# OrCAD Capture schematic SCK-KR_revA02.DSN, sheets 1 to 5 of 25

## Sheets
1 Title Page
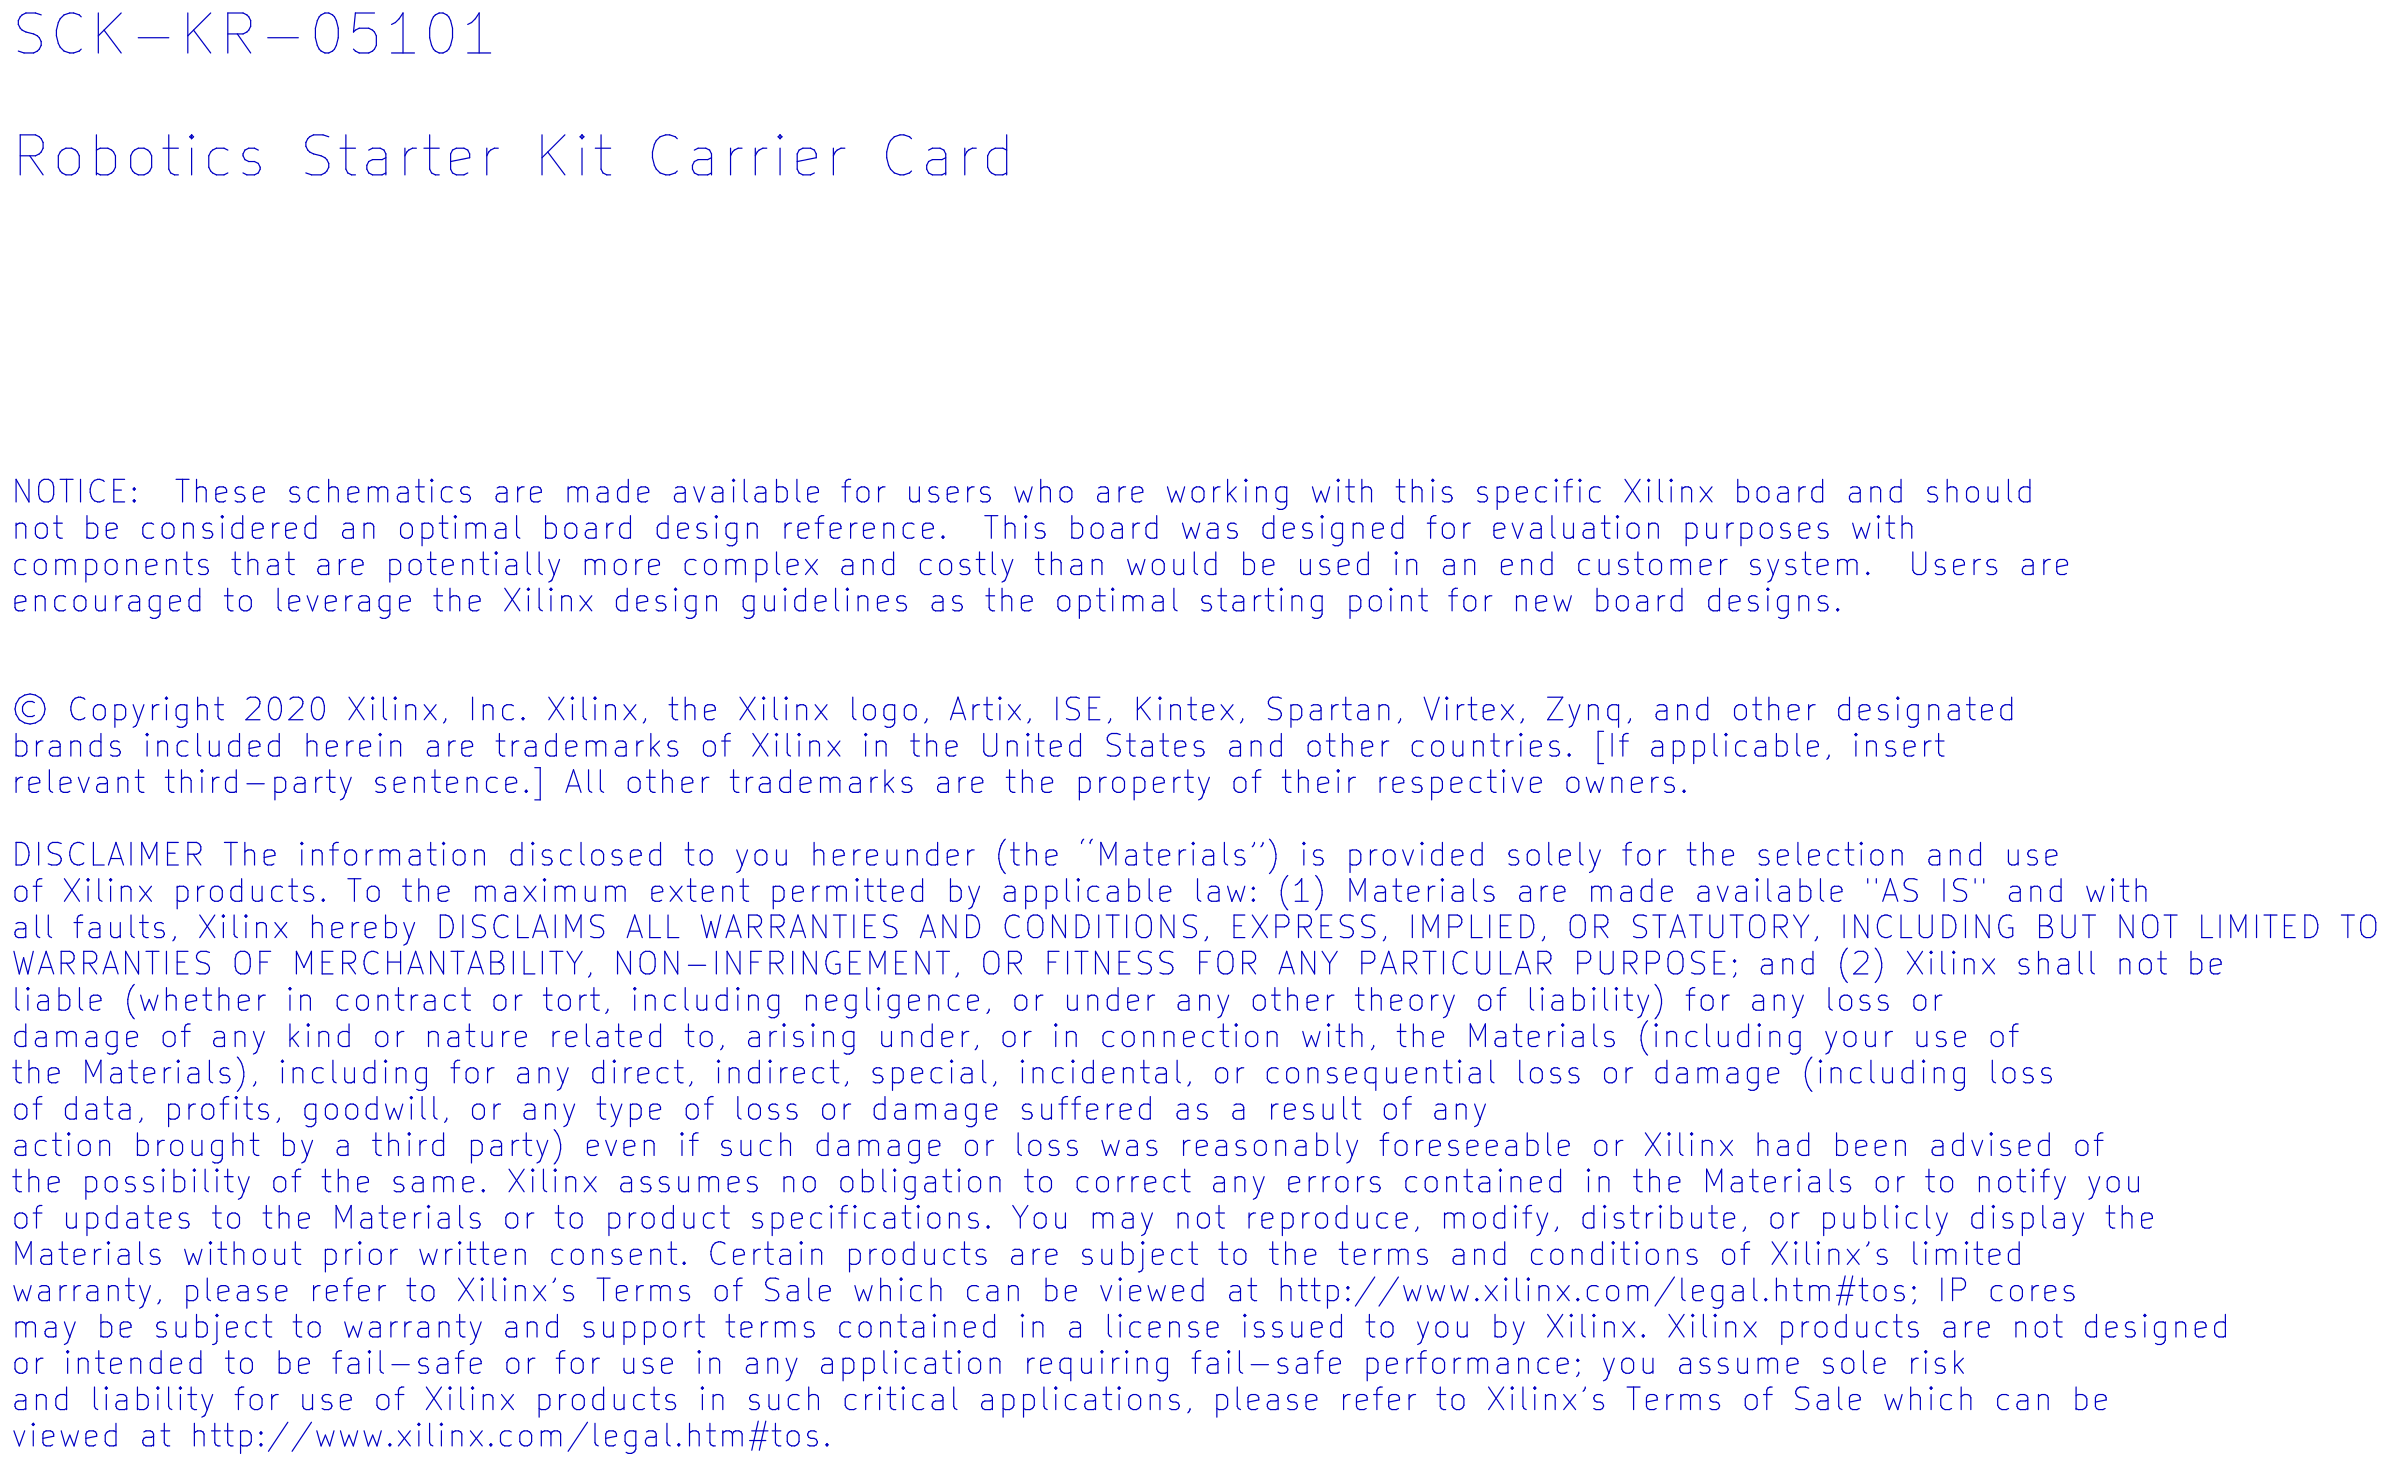
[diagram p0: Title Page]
2 Block Diagram
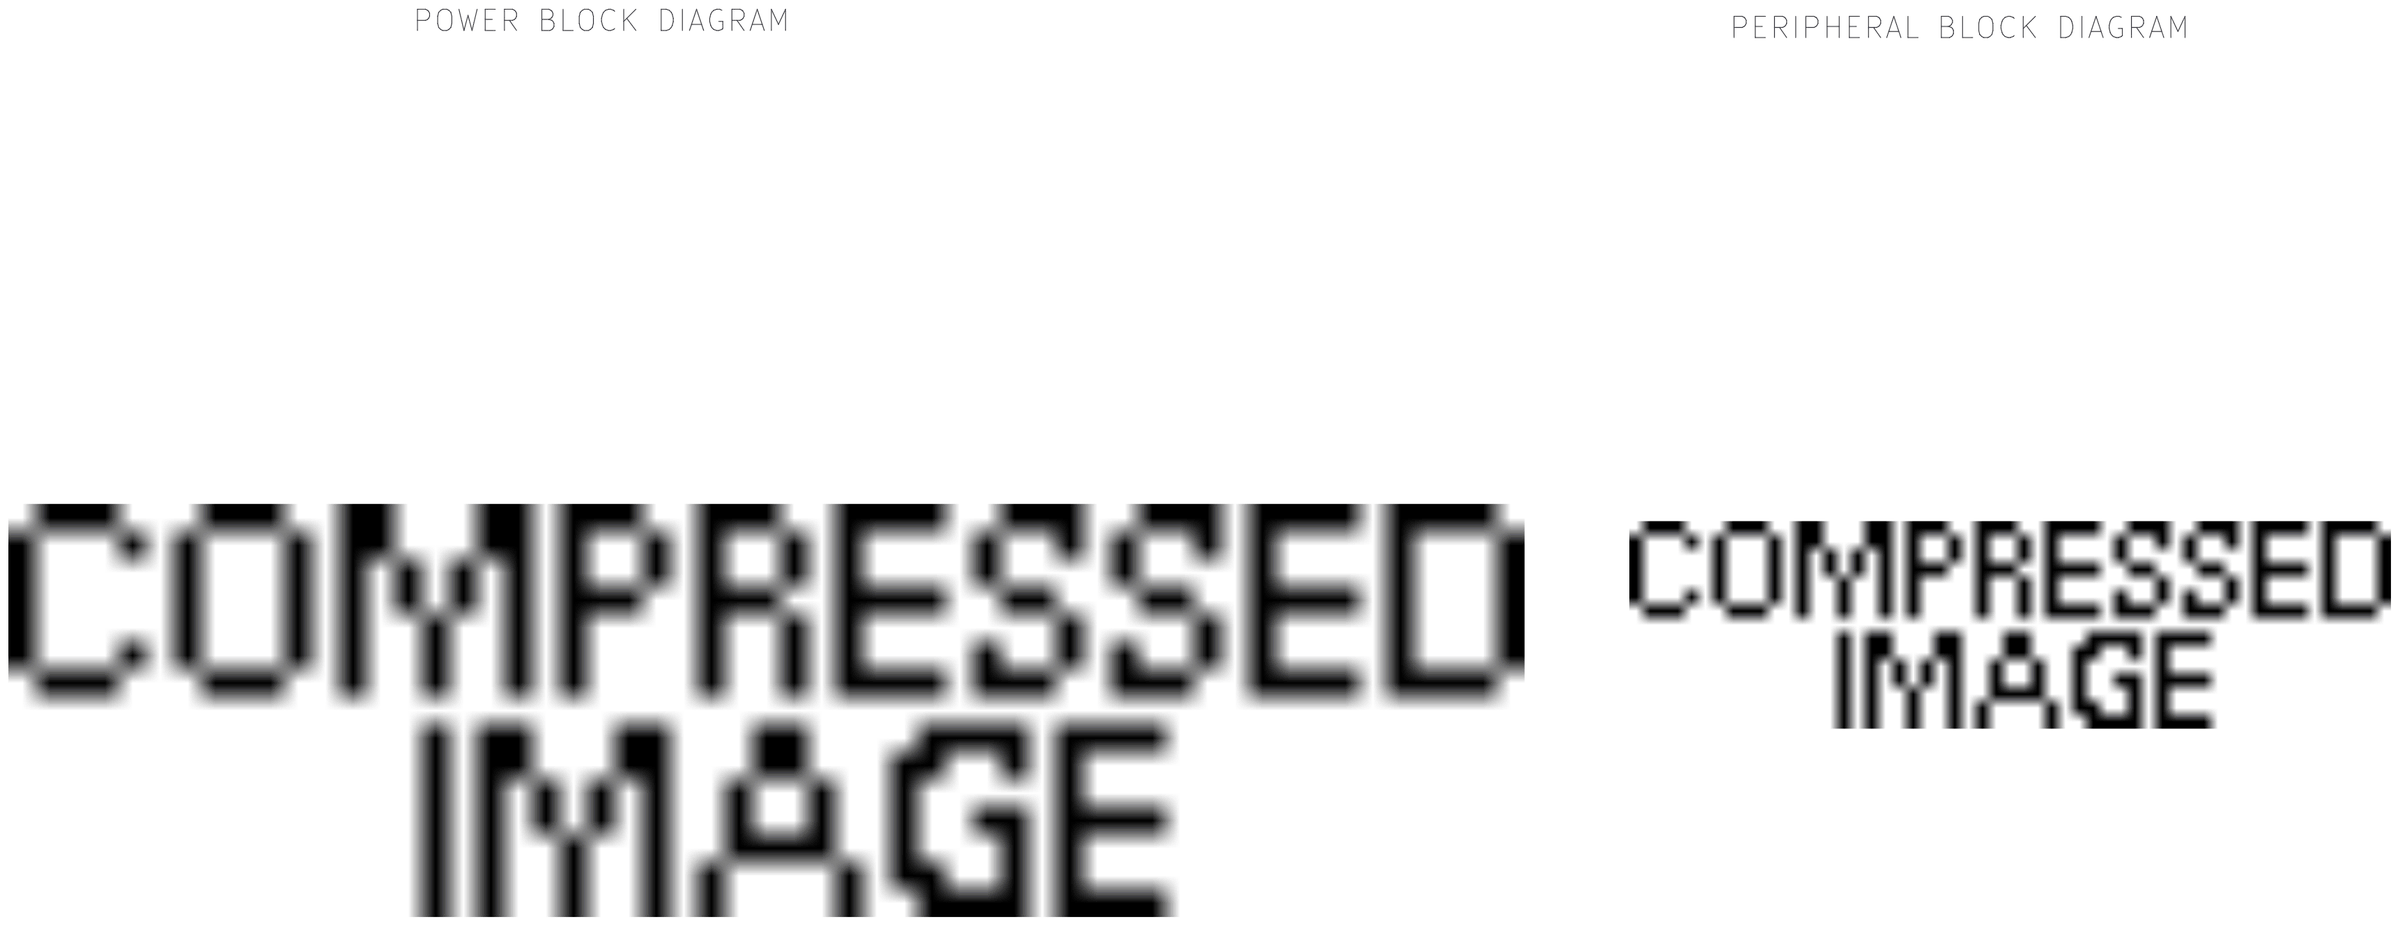
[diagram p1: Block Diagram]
3 Always On Pwr, Fan Header: size Custom
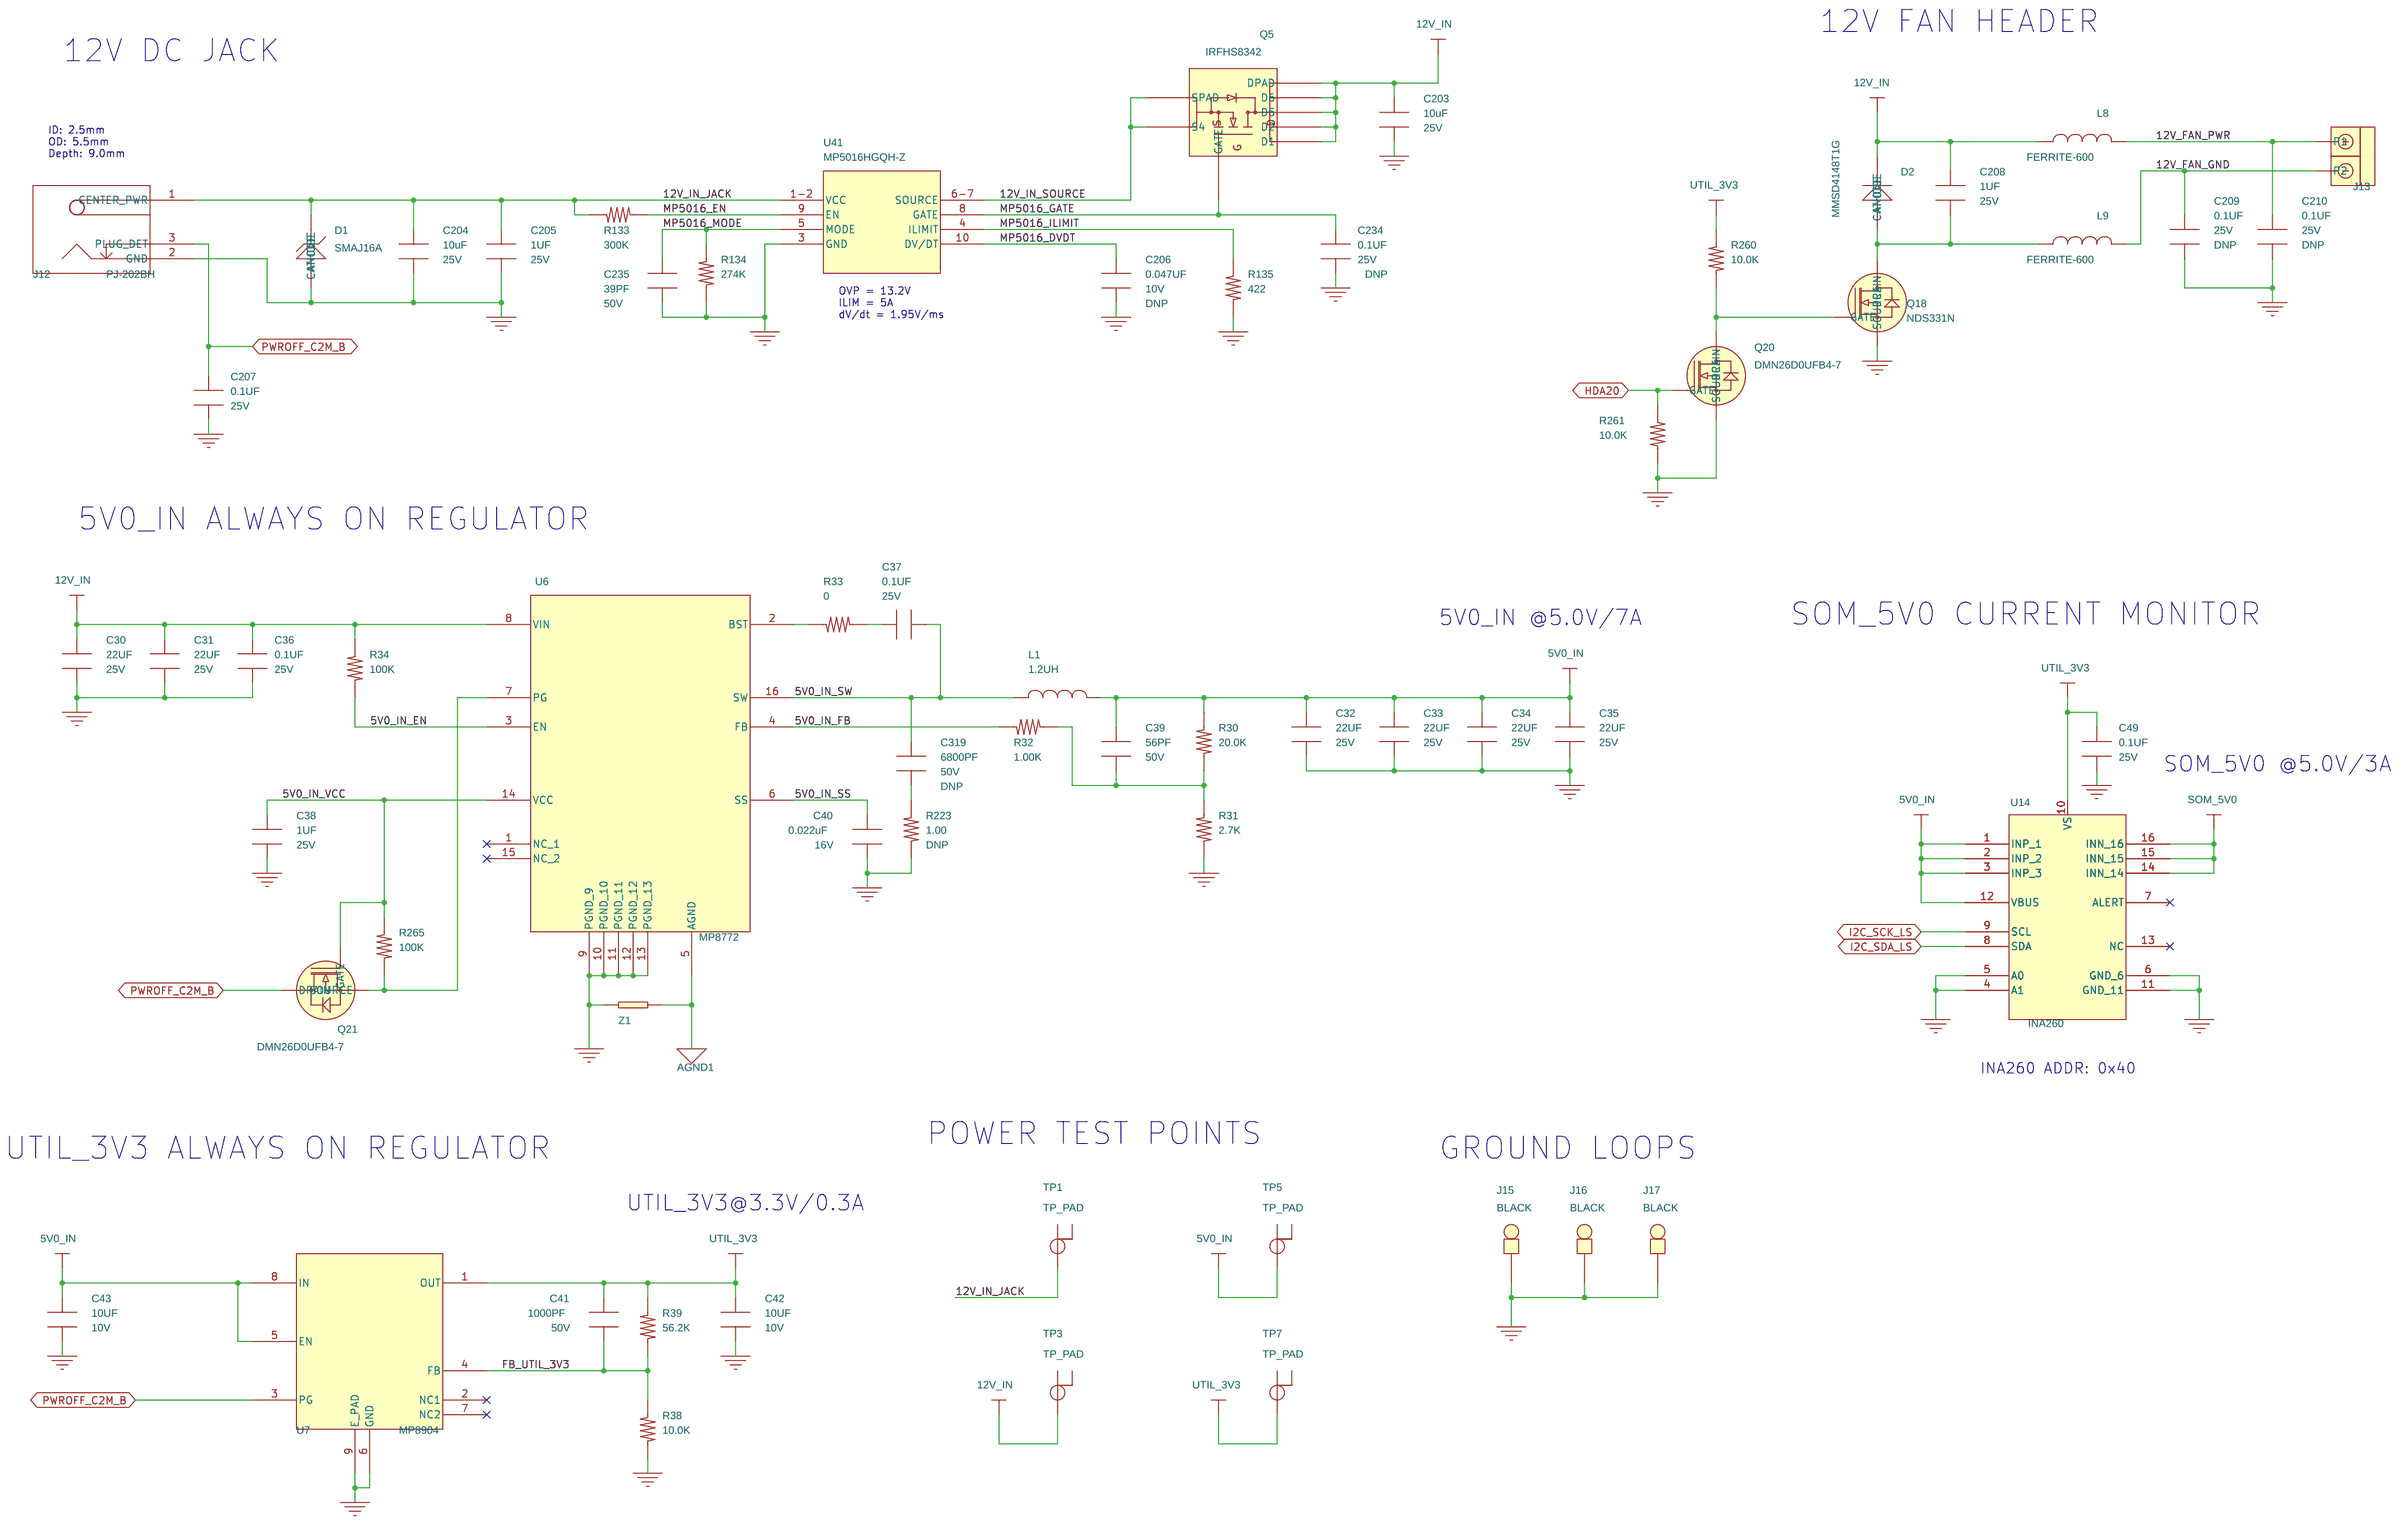
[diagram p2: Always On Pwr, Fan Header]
4 PS Power: size Custom
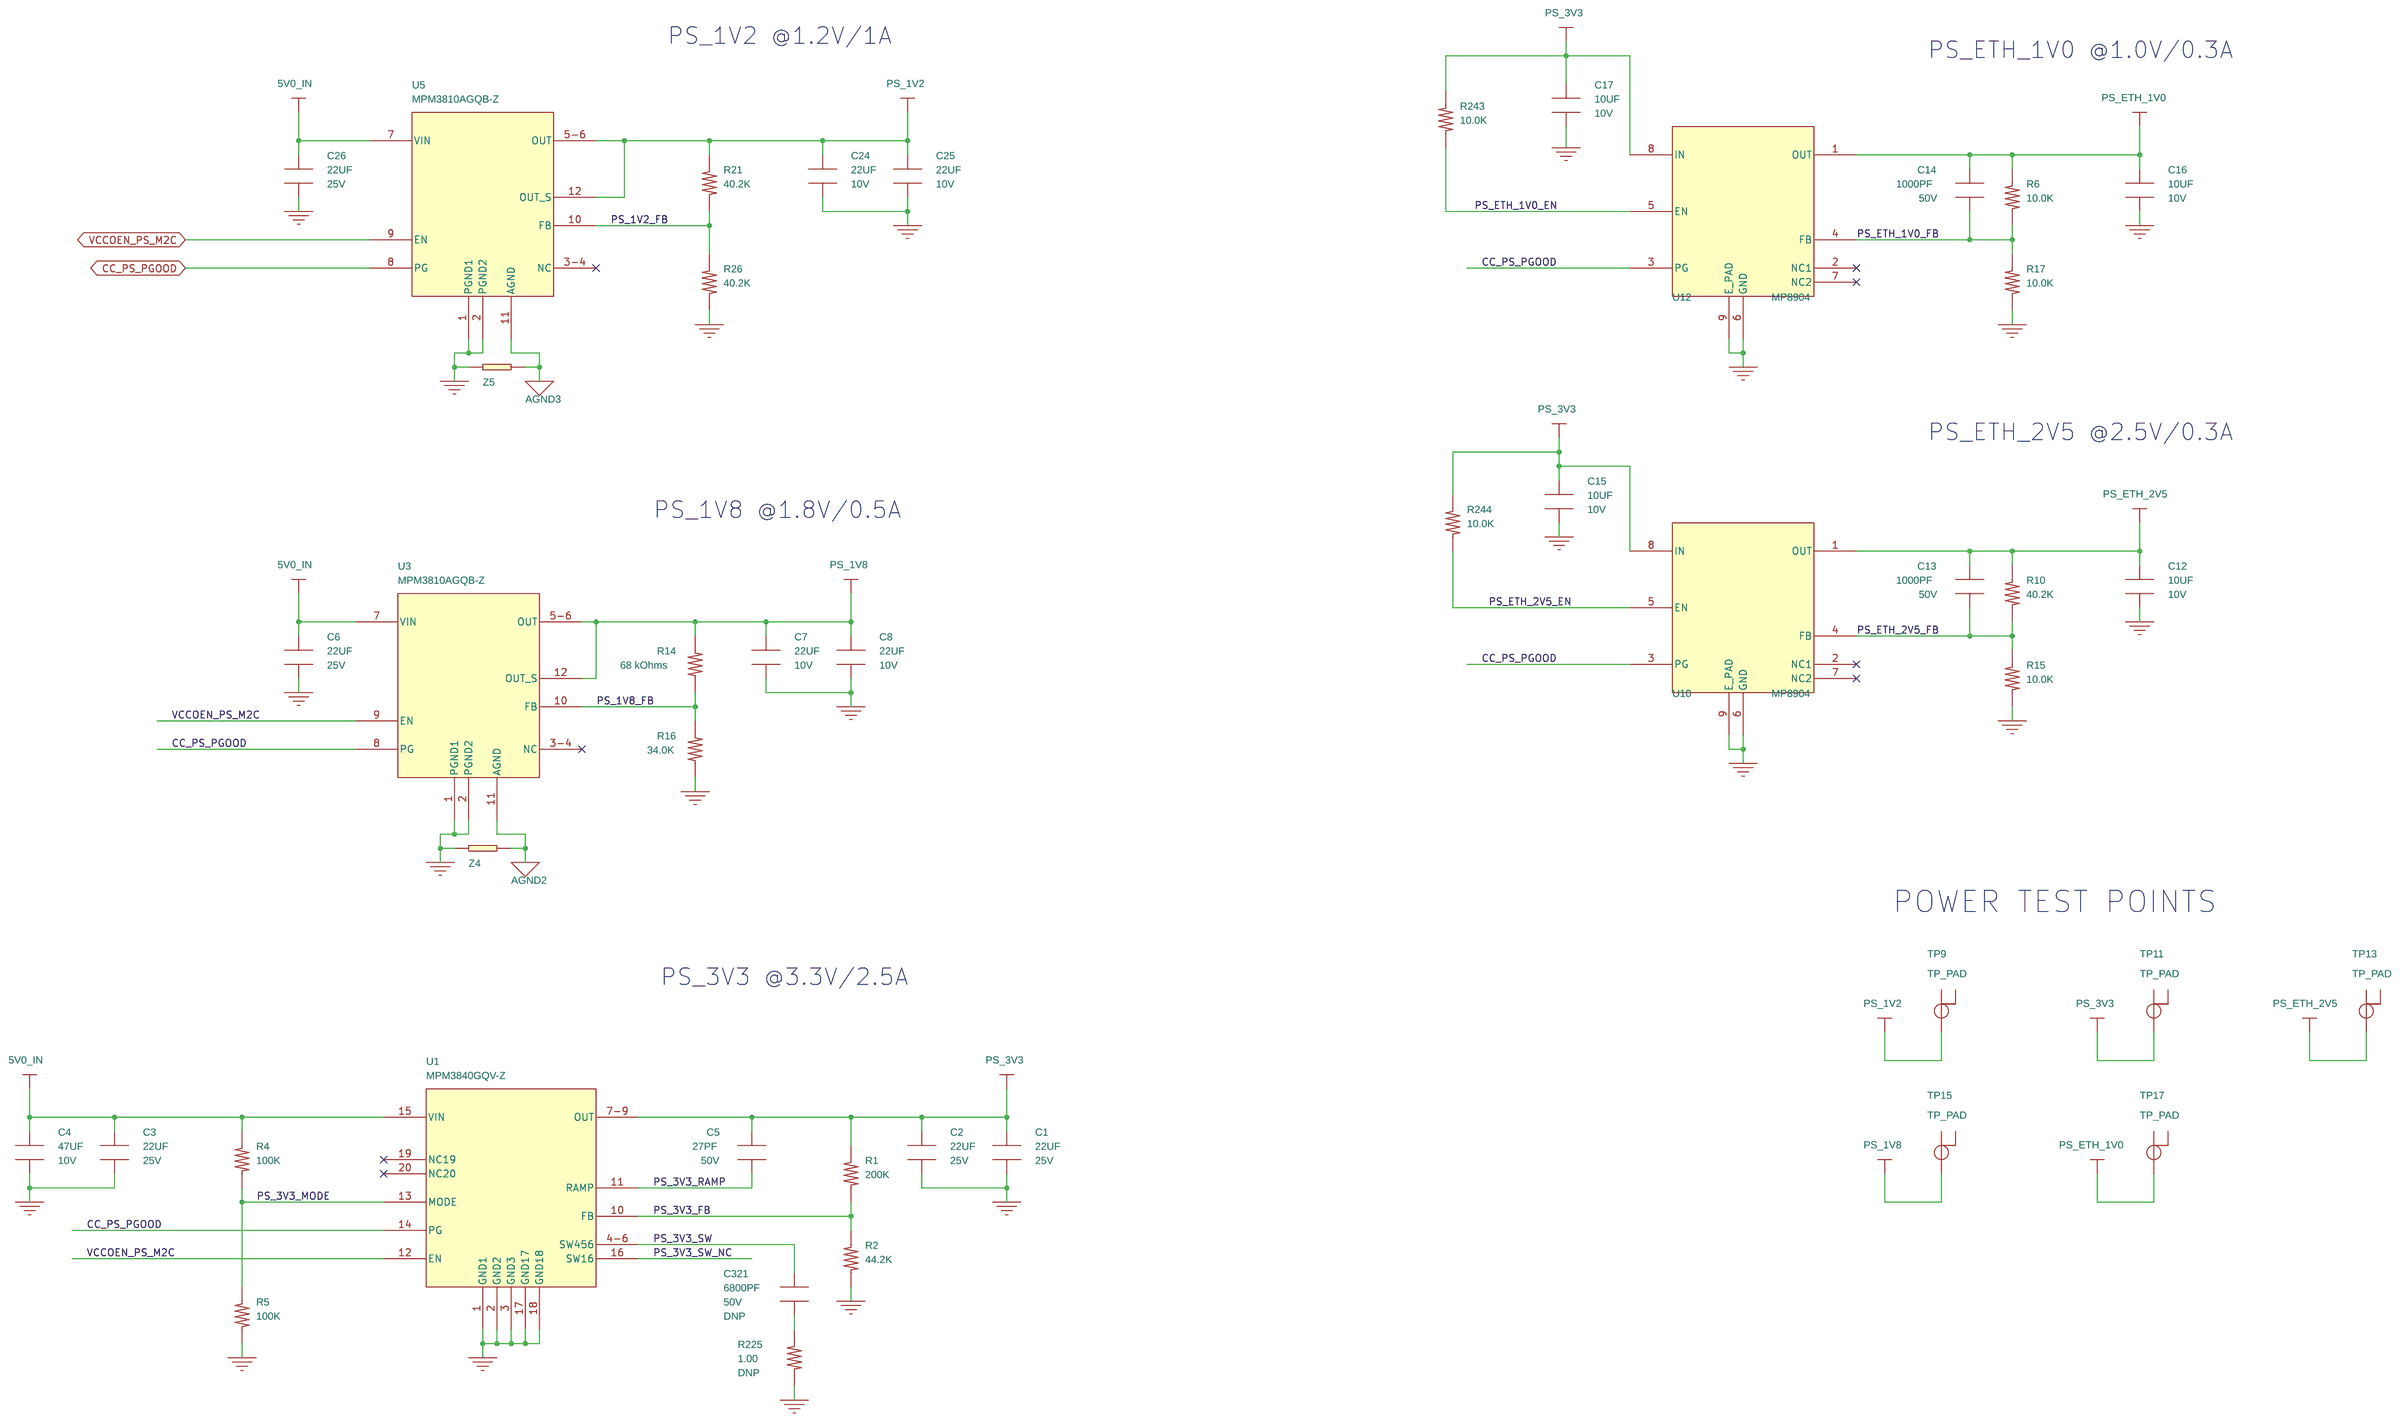
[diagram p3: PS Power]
5 PL Power: size Custom
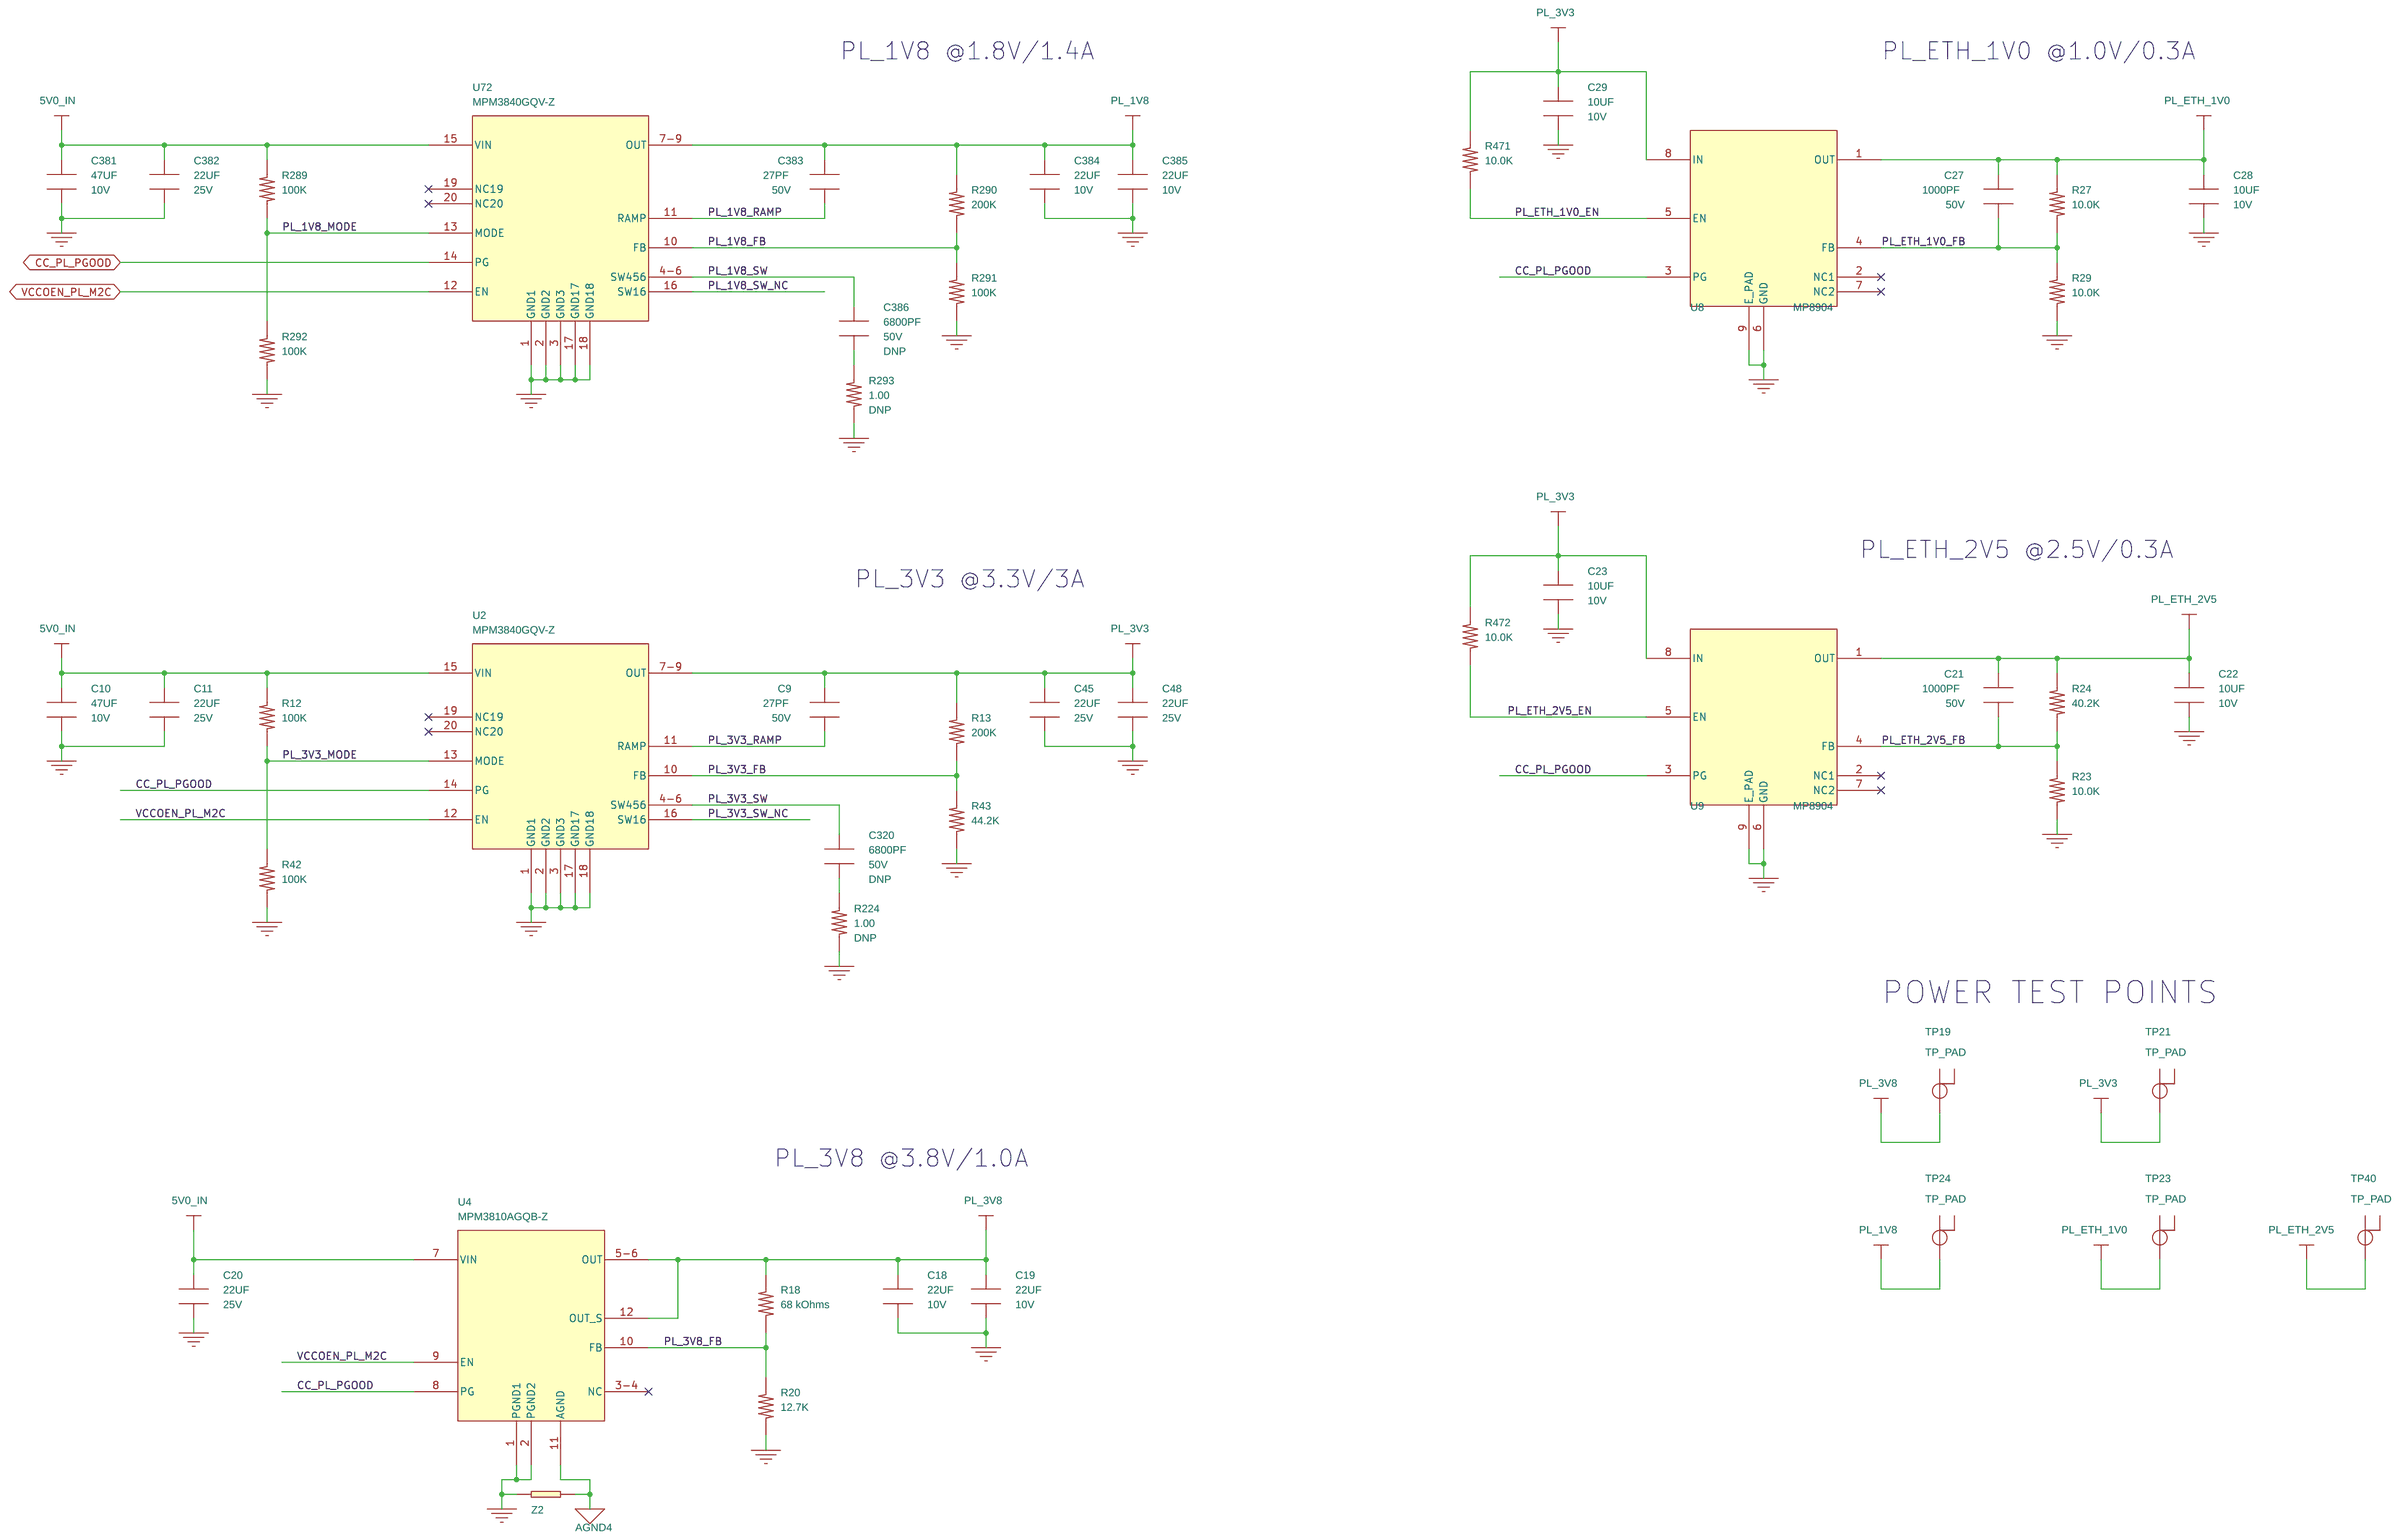
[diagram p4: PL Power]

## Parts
sheet Always On Pwr, Fan Header
C30  22UF  [CAPC200X125X145]
C31  22UF  [CAPC200X125X145]
C32  22UF  [CAPC200X125X145]
C33  22UF  [CAPC200X125X145]
C34  22UF  [CAPC200X125X145]
C35  22UF  [CAPC200X125X145]
C36  0.1UF  [CAPC100X50X55]
C37  0.1UF  [CAPC100X50X55]
C38  1UF  [CAPC100X50X70]
C39  56PF  [CAPC100X50X55]
C40  0.022uF  [CAPC100X50X55]
C41  1000PF  [CAPC100X50X55]
C42  10UF  [CAPC100X50X70]
C43  10UF  [CAPC100X50X70]
C49  0.1UF  [CAPC100X50X55]
C203  10uF  [CAPC200X125X145]
C204  10uF  [CAPC200X125X145]
C205  1UF  [CAPC100X50X70]
C206  0.047UF  [CAPC100X50X50]
C207  0.1UF  [CAPC100X50X55]
C208  1UF  [CAPC100X50X70]
C209  0.1UF  [CAPC100X50X55]
C210  0.1UF  [CAPC100X50X55]
C234  0.1UF  [CAPC100X50X55]
C235  39PF  [CAPC100X50X55]
C319  6800PF  [CAPC100X50X70]
D1  SMAJ16A  [DO_214AC]
D2  MMSD4148T1G  [SOD_123]
J12  PJ-202BH  [CON_CUI_PJ202AH]
J13  22-11-2022  [HDR_1X2_LOCK_MOLEX]
J15  BLACK  [TP_KEY_MINI]
J16  BLACK  [TP_KEY_MINI]
J17  BLACK  [TP_KEY_MINI]
L1  1.2UH  [IND_COIL_XEL5030]
L8  FERRITE-600  [INDC160X80X95]
L9  FERRITE-600  [INDC160X80X95]
Q5  IRFHS8342  [PQFN_65P210X2110X100-8]
Q18  NDS331N  [SOT_23]
Q20  DMN26D0UFB4-7  [DFN_105X65x40_3]
Q21  DMN26D0UFB4-7  [DFN_105X65x40_3]
R30  20.0K  [RESC100X50X40]
R31  2.7K  [RESC100X50X40]
R32  1.00K  [RESC100X50X40]
R33  0  [RESC160X80X65]
R34  100K  [RESC60X30X26]
R38  10.0K  [RESC100X50X40]
R39  56.2K  [RESC100X50X40]
R133  300K  [RESC100X50X40]
R134  274K  [RESC100X50X40]
R135  422  [RESC100X50X40]
R223  1.00  [RESC200X125X75]
R260  10.0K  [RESC100X50X40]
R261  10.0K  [RESC100X50X40]
R265  100K  [RESC60X30X26]
TP1  TP_PAD  [TP_PAD]
TP3  TP_PAD  [TP_PAD]
TP5  TP_PAD  [TP_PAD]
TP7  TP_PAD  [TP_PAD]
U6  MP8772  [QFN40P300X300X100-16_MP8772]
U7  MP8904  [QFN_MP8904DD_8]
U14  INA260  [TSSOP065P620X120_16]
U41  MP5016HGQH-Z  [PQFN10_MP5016HGQH]
Z1  0201_SHORT  [0201_SHORT]
sheet PL Power
C9  27PF  [CAPC100X50X55]
C10  47UF  [CAPC200X125X125]
C11  22UF  [CAPC200X125X145]
C18  22UF  [CAPC160X80X100]
C19  22UF  [CAPC160X80X100]
C20  22UF  [CAPC200X125X145]
C21  1000PF  [CAPC100X50X55]
C22  10UF  [CAPC100X50X70]
C23  10UF  [CAPC100X50X70]
C27  1000PF  [CAPC100X50X55]
C28  10UF  [CAPC100X50X70]
C29  10UF  [CAPC100X50X70]
C45  22UF  [CAPC200X125X145]
C48  22UF  [CAPC200X125X145]
C320  6800PF  [CAPC100X50X70]
C381  47UF  [CAPC200X125X125]
C382  22UF  [CAPC200X125X145]
C383  27PF  [CAPC100X50X55]
C384  22UF  [CAPC160X80X100]
C385  22UF  [CAPC160X80X100]
C386  6800PF  [CAPC100X50X70]
R12  100K  [RESC100X50X40]
R13  200K  [RESC100X50X40]
R18  68 kOhms  [RESC100X50X40]
R20  12.7K  [RESC100X50X40]
R23  10.0K  [RESC100X50X40]
R24  40.2K  [RESC100X50X40]
R27  10.0K  [RESC100X50X40]
R29  10.0K  [RESC100X50X40]
R42  100K  [RESC100X50X40]
R43  44.2K  [RESC100X50X40]
R224  1.00  [RESC200X125X75]
R289  100K  [RESC100X50X40]
R290  200K  [RESC100X50X40]
R291  100K  [RESC100X50X40]
R292  100K  [RESC100X50X40]
R293  1.00  [RESC200X125X75]
R471  10.0K  [RESC100X50X40]
R472  10.0K  [RESC100X50X40]
TP19  TP_PAD  [TP_PAD]
TP21  TP_PAD  [TP_PAD]
TP23  TP_PAD  [TP_PAD]
TP24  TP_PAD  [TP_PAD]
TP40  TP_PAD  [TP_PAD]
U2  MPM3840GQV-Z  [PQFN20_MPS_MPM3840GQV]
U4  MPM3810AGQB-Z  [QFN12_MPM3805A]
U8  MP8904  [QFN_MP8904DD_8]
U9  MP8904  [QFN_MP8904DD_8]
U72  MPM3840GQV-Z  [PQFN20_MPS_MPM3840GQV]
Z2  0201_SHORT  [0201_SHORT]
sheet PS Power
C1  22UF  [CAPC200X125X145]
C2  22UF  [CAPC200X125X145]
C3  22UF  [CAPC200X125X145]
C4  47UF  [CAPC200X125X125]
C5  27PF  [CAPC100X50X55]
C6  22UF  [CAPC200X125X145]
C7  22UF  [CAPC160X80X100]
C8  22UF  [CAPC160X80X100]
C12  10UF  [CAPC100X50X70]
C13  1000PF  [CAPC100X50X55]
C14  1000PF  [CAPC100X50X55]
C15  10UF  [CAPC100X50X70]
C16  10UF  [CAPC100X50X70]
C17  10UF  [CAPC100X50X70]
C24  22UF  [CAPC160X80X100]
C25  22UF  [CAPC160X80X100]
C26  22UF  [CAPC200X125X145]
C321  6800PF  [CAPC100X50X70]
R1  200K  [RESC100X50X40]
R2  44.2K  [RESC100X50X40]
R4  100K  [RESC100X50X40]
R5  100K  [RESC100X50X40]
R6  10.0K  [RESC100X50X40]
R10  40.2K  [RESC100X50X40]
R14  68 kOhms  [RESC100X50X40]
R15  10.0K  [RESC100X50X40]
R16  34.0K  [RESC100X50X40]
R17  10.0K  [RESC100X50X40]
R21  40.2K  [RESC100X50X40]
R26  40.2K  [RESC100X50X40]
R225  1.00  [RESC200X125X75]
R243  10.0K  [RESC100X50X40]
R244  10.0K  [RESC100X50X40]
TP9  TP_PAD  [TP_PAD]
TP11  TP_PAD  [TP_PAD]
TP13  TP_PAD  [TP_PAD]
TP15  TP_PAD  [TP_PAD]
TP17  TP_PAD  [TP_PAD]
U1  MPM3840GQV-Z  [PQFN20_MPS_MPM3840GQV]
U3  MPM3810AGQB-Z  [QFN12_MPM3805A]
U5  MPM3810AGQB-Z  [QFN12_MPM3805A]
U10  MP8904  [QFN_MP8904DD_8]
U12  MP8904  [QFN_MP8904DD_8]
Z4  0201_SHORT  [0201_SHORT]
Z5  0201_SHORT  [0201_SHORT]

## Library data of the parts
C1-C3 C6 C11 C20 C26 C30-C35 C382 = CAP_NP: Cap Cer 22uF 20% 25V X5R 0805; Agile Part Number: CAP-00209-01; Barcode: 100281; CIP Link: http://xsjbrdwin1/CIP-E/Component/Index/All?pn=100281; Dielectric Type: X5R; Manufacturer: MURATA; Manufacturer PN: GRM21BR61E226ME44L; Part Type: CERAMIC; Tolerance: 20%; Voltage: 25V
C36 C37 C49 C207 = CAP_NP: Cap Cer 100nF 10% 25V X5R 0402; ALT_SYMBOLS: CAPC100X50X55RND; Agile Part Number: CAP-00068-01; CIP Link: http://xsjbrdwin1/CIP-E/Component/Index/All?pn=100040; DEVICE: 0_1UF_0402_X7R_50V; Dielectric: X7R; Dielectric Type: X5R; MANF: TAIYO YUDEN; MANF_P/N: UMK105B7104KV-FR; Manufacturer: TAIYO YUDEN; Manufacturer PN: TMK105BJ104KV-F; OWNER: 6176; PRICE: 0.02; Part Type: CERAMIC; PartType: CERAMIC; ROHS: Yes; Tolerance: 10%; Voltage: 25V; barcode: 100040
C38 C205 C208 = CAP_NP: Cap Cer 1uF 10% 25V X6S 0402; ALT_SYMBOLS: CAPC100X50X55RND; Agile Part Number: CAP-00009-01; Barcode: 100269; CIP Link: http://xsjbrdwin1/CIP-E/Component/Index/All?pn=100269; Dielectric Type: X6S; Manufacturer: MURATA; Manufacturer PN: GRM155C81E105KE11D; Part Type: CERAMIC; Tolerance: 10%; Voltage: 25V
C39 = CAP_NP: Cap Cer 56pF 5% 50V C0G 0402; ALT_SYMBOLS: CAPC100X50X55RND; Agile Part Number: CAP-00208-01; Barcode: 100279; CIP Link: http://xsjbrdwin1/CIP-E/Component/Index/All?pn=100279; Dielectric Type: C0G, NP0; Manufacturer: MURATA; Manufacturer PN: GCM1555C1H560JA16D; Part Type: CERAMIC; Tolerance: 5%; Voltage: 50V
C40 = CAP_NP: Cap Cer 22nF 10% 16V X7R 0402; Agile Part Number: CAP-00041-01; Barcode: 10000001; CIP Link: http://xsjbrdwin1/CIP-E/Component/Index/All?pn=10000001; Dielectric Type: X7R; Manufacturer: Taiyo Yuden; Manufacturer PN: EMK105B7223KV-F; Part Type: CERAMIC; Tolerance: 10%; Voltage: 16V; Datasheet: http://download.siliconexpert.com/pdfs2/2019/4/19/21/40/25/794111/tay_/manual/emk105b7223kv-f_ss.pdf
C13 C14 C21 C27 C41 = CAP_NP: Cap Cer 1nF 10% 50V X7R 0402; ALT_SYMBOLS: CAPC100X50X55RND; Agile Part Number: CAP-00036-01; Barcode: 100013; CIP Link: http://xsjbrdwin1/CIP-E/Component/Index/All?pn=100013; Dielectric Type: X7R; Manufacturer: MURATA; Manufacturer PN: GCM155R71H102KA37D; Part Type: CERAMIC; Tolerance: 10%; Voltage: 50V
C12 C15-C17 C22 C23 C28 C29 C42 C43 = CAP_NP: Cap Cer 10uF 20% 10V X5R 0402; Agile Part Number: CAP-00170-01; Barcode: 100197; CIP Link: http://xsjbrdwin1/CIP-E/Component/Index/All?pn=100197; Dielectric Type: X5R; Manufacturer: SAMSUNG; Manufacturer PN: CL05A106MP5NUNC; Part Type: CERAMIC; Tolerance: 20%; Voltage: 10V
C203 C204 = CAP_NP: Cap Cer 10uF 10% 25V X7S 0805; Agile Part Number: CAP-00294-01; Barcode: 10000021; CIP Link: http://xsjbrdwin1/CIP-E/Component/Index/All?pn=10000021; Manufacturer: Murata Electronics; Manufacturer PN: GRM21BC71E106KE11L; Part Type: CERAMIC; Tolerance: 10%; Voltage: 25V; Datasheet: https://search.murata.co.jp/Ceramy/image/img/A01X/G101/ENG/GRM21BC71E106KE11-01.pdf
C206 = CAP_NP: Cap Cer 47nF 10% 10V X5R 0402; ASSEMBLY_OPTIONS: DNP; Agile Part Number: CAP-00078-01; Barcode: 100057; CIP Link: http://xsjbrdwin1/CIP-E/Component/Index/All?pn=100057; Dielectric Type: X5R; Manufacturer: TDK; Manufacturer PN: C1005X5R1A473K050BA; Part Type: CERAMIC; Tolerance: 10%; Voltage: 10V
C209 C210 C234 = CAP_NP: Cap Cer 100nF 10% 25V X5R 0402; ALT_SYMBOLS: CAPC100X50X55RND; ASSEMBLY_OPTIONS: DNP; Agile Part Number: CAP-00068-01; CIP Link: http://xsjbrdwin1/CIP-E/Component/Index/All?pn=100040; DEVICE: 0_1UF_0402_X7R_50V; Dielectric: X7R; Dielectric Type: X5R; MANF: TAIYO YUDEN; MANF_P/N: UMK105B7104KV-FR; Manufacturer: TAIYO YUDEN; Manufacturer PN: TMK105BJ104KV-F; OWNER: 6176; PRICE: 0.02; Part Type: CERAMIC; PartType: CERAMIC; ROHS: Yes; Tolerance: 10%; Voltage: 25V; barcode: 100040
C235 = CAP_NP: Cap Cer 39pF 1% 50V C0G 0402; ALT_SYMBOLS: CAPC100X50X55RND; Agile Part Number: CAP-00247-01; Barcode: 100328; CIP Link: http://xsjbrdwin1/CIP-E/Component/Index/All?pn=100328; Dielectric Type: NP0; Manufacturer: KEMET; Manufacturer PN: C0402C390F5GACTU; Part Type: CERAMIC; Tolerance: 5%; Voltage: 50V
C319-C321 C386 = CAP_NP: Cap Cer 6.8nF 10% 50V X7R 0402; ALT_SYMBOLS: (0402,C402-25,CAPC100X50X55L25NRND,CAPC100X50X55L30NRND,CAPC100X50X55L30N); ASSEMBLY_OPTIONS: DNP; Agile Part Number: CAP-00145-01; Barcode: 100167; CIP Link: http://xsjbrdwin1/CIP-E/Component/Index/All?pn=100167; Dielectric Type: X7R; Manufacturer: KEMET; Manufacturer PN: C0402C682K5RACTU; Part Type: CERAMIC; Tolerance: 10%; Voltage: 50V
D1 = DIODE_ZENER: TVS 1-Ch 16V 15.4A 400W SMA 40A IFSM; Agile Part Number: DIO-00075-01; Barcode: 70000010; CIP Link: http://xsjbrdwin1/CIP-E/Component/Index/All?pn=70000010; Manufacturer: Littelfuse Inc.; Part Type: TVS; Rated Power: 400W; Voltage: 16V; Datasheet: https://www.littelfuse.com/~/media/electronics/datasheets/tvs_diodes/littelfuse_tvs_diode_smaj_datasheet.pdf.pdf
D2 = BAT54T1G: Diode Switching 200mA 100V 4nSec SOD-123; Agile Part Number: DIO-00081-01; Barcode: 70000018; CIP Link: http://xsjbrdwin1/CIP-E/Component/Index/All?pn=70000018; Manufacturer: ON Semiconductor; Part Type: SWITCHING; Voltage: 1V @ 10mA; Datasheet: http://www.onsemi.com/pub/Collateral/MMSD4148T1-D.PDF
J12 = PJ-202AH: Conn Rcpt Power Jack Male RA 2.5mm Pin 5A 24VDC Black TH; Agile Part Number: CON-00408-01; Barcode: 40000094; CIP Link: http://xsjbrdwin1/CIP-E/Component/Index/All?pn=40000094; Manufacturer: CUI Devices; Part Type: POWER CONNECTOR
J13 = HDR_REMOTE_SENSE_A: Conn Hdr Male Vert 2 Pos 1x2 2.54mm P Natural TH Friction Lock; Agile Part Number: CON-00103-01; Barcode: 400017; CIP Link: http://xsjbrdwin1/CIP-E/Component/Index/All?pn=400017; Manufacturer: MOLEX; Manufacturer PN: 0022112022; Part Type: HEADER; Pitch: 0.100
J15-J17 = TP-HOOK: Conn Test Point Mini Loop Black TH; ALT_SYMBOLS: TP_KEY_MINI_DNP; Agile Part Number: CON-00272-01; Barcode: 900015; CIP Link: http://xsjbrdwin1/CIP-E/Component/Index/All?pn=900015; Manufacturer: KEYSTONE; Manufacturer PN: 5001; Part Type: TEST POINT; Pitch: 0.04IN
L1 = IND: Ind 1.2uH 20% 11A Irms 15A Isat 10.5mR 5.5x5.3mm SMT Shielded; Agile Part Number: IND-00170-01; Barcode: 30000007; CIP Link: http://xsjbrdwin1/CIP-E/Component/Index/All?pn=30000007; Manufacturer: COILCRAFT; Manufacturer PN: XEL5030-122ME; Part Type: POWER INDUCTOR; Tolerance: 30 %
L8 L9 = IND: Bead 600R 25% 1.3A 150mR 0603; Agile Part Number: FLT-00024-01; Barcode: 30000019; CIP Link: http://xsjbrdwin1/CIP-E/Component/Index/All?pn=30000019; Manufacturer: Murata Electronics North America; Manufacturer PN: BLM18KG601SN1D; Part Type: FERRITE; Rated Current: 1.3A; Datasheet: https://media.digikey.com/pdf/Data%20Sheets/Murata%20PDFs/BLM18yyyyyyN1x.pdf
Q5 = IRFHS8342: MOSFET N-Ch 30V 19A 16mR 2x2mm PQFN-8; Agile Part Number: TRN-00056-01; Barcode: 83000007; CIP Link: http://xsjbrdwin1/CIP-E/Component/Index/All?pn=83000007; Manufacturer: Infineon Technologies; Manufacturer PN: IRFHS8342TRPBF; Part Type: FET; Rated Power: 2.1W (Ta); Datasheet: https://www.infineon.com/dgdl/irfhs8342pbf.pdf?fileId=5546d462533600a401535623992e1f5f
Q18 = FET-3PIN: MOSFET N-Ch 20V 1.3A 160mR SSOT-3; Agile Part Number: TRN-00012-01; Barcode: 500100; CIP Link: http://xsjbrdwin1/CIP-E/Component/Index/All?pn=500100; Manufacturer: FAIRCHILD; Part Type: FET; Rated Power: 460MW; Rated Voltage: 20V
Q20 Q21 = DMN26D0UFB4: MOSFET N-CH 20V 230MA DFN; Agile Part Number: TRN-00054-01; Barcode: 83000008; CIP Link: http://xsjbrdwin1/CIP-E/Component/Index/All?pn=83000008; Manufacturer: Diodes Incorporated; Part Type: FET; Rated Power: 350mW (Ta); Datasheet: https://www.diodes.com/assets/Datasheets/ds31775.pdf
R30 = RES: Res 20K 1% 1/16W 100PPM 50V 0402; ALT_SYMBOLS: RESC100X50X40RND; Agile Part Number: RES-00136-01; Barcode: 200124; CIP Link: http://xsjbrdwin1/CIP-E/Component/Index/All?pn=200124; Manufacturer: PANASONIC; Manufacturer PN: ERJ2RKF2002X; Part Type: SMT - 1%; Rated Power: 1/10W; Tolerance: 1%
R31 = RES: Res 2K7 1% 1/16W 100PPM 50V 0402; ALT_SYMBOLS: (0402,C402-25,RESC100X50X40L25NRND); Agile Part Number: RES-00144-01; Barcode: 200134; CIP Link: http://xsjbrdwin1/CIP-E/Component/Index/All?pn=200134; Manufacturer: PANASONIC; Manufacturer PN: ERJ2RKF2701X; Part Type: SMT - 1%; Rated Power: 1/16W; Tolerance: 1%
R32 = RES: Res 1K 1% 1/16W 100PPM 50V 0402; ALT_SYMBOLS: RESC100X50X40RND; Agile Part Number: RES-00027-01; Barcode: 200098; CIP Link: http://xsjbrdwin1/CIP-E/Component/Index/All?pn=200098; Manufacturer: PANASONIC; Manufacturer PN: ERJ2RKF1001X; OWNER: 4001; PRICE: 0; Part Type: SMT - 1%; PartType: SMT - 1%; Power: 1/16W; ROHS: Yes; Rated Power: 1/16W; Tolerance: 1%; primarykey: 7
R33 = RES: Res 0R 50mR 1A 0603; Agile Part Number: RES-00142-01; Barcode: 200132; CIP Link: http://xsjbrdwin1/CIP-E/Component/Index/All?pn=200132; Manufacturer: PANASONIC; Manufacturer PN: ERJ3GEY0R00V; Part Type: SMT - 5%; Rated Power: 1/10W; Tolerance: 5%
R34 R265 = RES: Res 100K 1% 1/20W 200PPM 25V 0201; ALT_SYMBOLS: RESC60X30X26RND; Agile Part Number: RES-00374-01; Barcode: 200412; CIP Link: http://xsjbrdwin1/CIP-E/Component/Index/All?pn=200412; Manufacturer: PANASONIC; Manufacturer PN: ERJ1GEF1003C; Part Type: SMT - 1%; Rated Power: 1/20W; Tolerance: 1%
R6 R15 R17 R23 R27 R29 R38 R243 R244 R260 R261 R471 R472 = RES: Res 10K 1% 1/16W 100PPM 50V 0402; ALT_SYMBOLS: RESC100X50X40RND; Agile Part Number: RES-00030-01; Barcode: 200025; CIP Link: http://xsjbrdwin1/CIP-E/Component/Index/All?pn=200025; Manufacturer: PANASONIC; Manufacturer PN: ERJ2RKF1002X; Part Type: SMT - 1%; Rated Power: 1/16W; Tolerance: 1%
R39 = RES: Res 56K2 1% 1/16W 100PPM 50V 0402; Agile Part Number: RES-00044-01; Barcode: 200256; CIP Link: http://xsjbrdwin1/CIP-E/Component/Index/All?pn=200256; Manufacturer: PANASONIC; Manufacturer PN: ERJ2RKF5622X; Part Type: SMT - 1%; Rated Power: 1/16W; Tolerance: 1%
R133 = RES: Res 300K 1% 1/16W 100PPM 50V 0402; ALT_SYMBOLS: (0402,C402-25,RESC100X50X40L25NRND); Agile Part Number: RES-00310-01; Barcode: 200343; CIP Link: http://xsjbrdwin1/CIP-E/Component/Index/All?pn=200343; Manufacturer: PANASONIC; Manufacturer PN: ERJ2RKF3003X; Part Type: SMT - 1%; Rated Power: 1/16W; Tolerance: 1%
R134 = RES: Res 274K1% 1/16W 100PPM 50V 0402; Agile Part Number: RES-00407-01; Barcode: 200463; CIP Link: http://xsjbrdwin1/CIP-E/Component/Index/All?pn=200463; Manufacturer: PANASONIC; Manufacturer PN: ERJ2RKF2743X; Part Type: SMT - 1%; Rated Power: 1/16W; Tolerance: 1%
R135 = RES: Res 422R 1% 1/16W 100PPM 50V 0402; Agile Part Number: RES-00311-01; Barcode: 200345; CIP Link: http://xsjbrdwin1/CIP-E/Component/Index/All?pn=200345; Manufacturer: PANASONIC; Manufacturer PN: ERJ2RKF4220X; Part Type: SMT - 1%; Rated Power: 1/16W; Tolerance: 1%
R223-R225 R293 = RES: RES SMD 1 OHM 5% 1/2W 0805; ASSEMBLY_OPTIONS: DNP; Agile Part Number: RES-00321-01; Barcode: 200355; CIP Link: http://xsjbrdwin1/CIP-E/Component/Index/All?pn=200355; Manufacturer: PANASONIC; Manufacturer PN: ERJ-P6WJ1R0V; Part Type: SMT - 1%; Rated Power: 1/2W; Tolerance: 5%
TP1 TP3 TP5 TP7 TP9 TP11 TP13 TP15 TP17 TP19 TP21 TP23 TP24 TP40 = TP: TEST POINT 24mil SM pad; ASSEMBLY_OPTIONS: DNP; Barcode: 96000010; CIP Link: http://xsjbrdwin1/CIP-E/Component/Index/All?pn=96000010; MANF: DNP; MANF_P/N: DNP; OWNER: 3709; Part Type: Unassigned Part Type; PartType: TEST POINT; Pins: 1PIN; ROHS: Yes; Datasheet: NA
U6 = MP8771: IC V. Reg Step-Down DC/DC Synch 17V 12A 700KHz QFN-16; ALT_SYMBOLS: QFN40P300X300X100-16; Agile Part Number: ICS-00550-01; Barcode: 50000087; CIP Link: http://xsjbrdwin1/CIP-E/Component/Index/All?pn=50000087; Manufacturer: Monolithic Power Systems Inc.; Manufacturer PN: MP8772GQ-Z; Part Type: POWER CONTROLLER; Datasheet: https://www.monolithicpower.com/en/documentview/productdocument/index/version/2/document_type/Datasheet/lang/EN/sku/MP8772/document_id/3720/
U7-U10 U12 = MP8904: IC LDO 6.5V 500mA Adj QFN-8; Agile Part Number: ICS-00581-01; Barcode: 96000022; CIP Link: http://xsjbrdwin1/CIP-E/Component/Index/All?pn=96000022; Manufacturer: Monolithic Power Systems Inc.; Manufacturer PN: MP8904DD-LF-Z; Part Type: LDO; Datasheet: https://www.monolithicpower.com/pub/media/document/MP8904_r1.02.pdf
U14 = INA260AIPW: IC Power Mon I2C 36Vin TSSOP-16; Agile Part Number: ICS-00017-01; Barcode: 500732; CIP Link: http://xsjbrdwin1/CIP-E/Component/Index/All?pn=500732; Manufacturer: Texas Instruments; Manufacturer PN: INA260AIPWR; Part Type: POWER MANAGEMENT; Datasheet: http://download.siliconexpert.com/pdfs/2018/9/21/3/31/55/742530/txn_/manual/getliterature.pdf
U41 = MP5016H: IC PWR LMT SWITCH N-CH 1:1 10QFN; Agile Part Number: ICS-00680-01; Barcode: 50000171; CIP Link: http://xsjbrdwin1/CIP-E/Component/Index/All?pn=50000171; Manufacturer: Monolithic Power Systems Inc.; Part Type: LOAD SWITCH; Supply Voltage: 2.7V ~ 22V; Datasheet: https://www.monolithicpower.com/pub/media/document/MP5016H_r1.0.pdf
Z1 Z2 Z4 Z5 = 0201_SHORT: PCB only 0201_SHORT; ASSEMBLY_OPTIONS: DNP; Barcode: 96000001; CIP Link: http://xsjbrdwin1/CIP-E/Component/Index/All?pn=96000001; Part Type: PCB LAYOUT
C5 C9 C383 = CAP_NP: Cap Cer 27pF 5% 50V C0G 0402; ALT_SYMBOLS: CAPC100X50X55RND; Agile Part Number: CAP-00037-01; Barcode: 100217; CIP Link: http://xsjbrdwin1/CIP-E/Component/Index/All?pn=100217; Dielectric Type: NP0; Manufacturer: TDK; Manufacturer PN: CGA2B2C0G1H270J050BA; Part Type: CERAMIC; Tolerance: 5%; Voltage: 50V
C4 C10 C381 = CAP_NP: CAP CER 47UF 10V X5R 0805; ALT_SYMBOLS: CAPC200X125X125RND; Agile Part Number: CAP-00254-01; Barcode: 100335; CIP Link: http://xsjbrdwin1/CIP-E/Component/Index/All?pn=100335; Dielectric Type: X5R; Manufacturer: MURATA; Manufacturer PN: GRM21BR61A476ME15L; Part Type: CERAMIC; Tolerance: 20%; Voltage: 10V
C7 C8 C18 C19 C24 C25 C384 C385 = CAP_NP: Cap Cer 22uF 20% 10V X5R 0603; ALT_SYMBOLS: 0603; Agile Part Number: CAP-00207-01; Barcode: 100277; CIP Link: http://xsjbrdwin1/CIP-E/Component/Index/All?pn=100277; Dielectric Type: X5R; Manufacturer: TDK; Manufacturer PN: C1608X5R1A226M080AC; Part Type: CERAMIC; Tolerance: 20%; Voltage: 10V
C45 C48 = CAP_NP: Cap Cer 22uF 20% 25V X5R 0805; Agile Part Number: CAP-00209-01; Barcode: 100281; CIP Link: http://xsjbrdwin1/CIP-E/Component/Index/All?pn=100281; Dielectric Type: X5R; Manufacturer: TDK; Manufacturer PN: C1608X5R1A226M080AC; Part Type: CERAMIC; Tolerance: 20%; Voltage: 25V
R4 R5 R12 R42 R289 R291 R292 = RES: Res 100K 5% 1/16W 200PPM 50V 0402; Agile Part Number: RES-00137-01; Barcode: 200127; CIP Link: http://xsjbrdwin1/CIP-E/Component/Index/All?pn=200127; Manufacturer: PANASONIC; Manufacturer PN: ERJ2GEJ104X; Part Type: SMT - 5%; Rated Power: 1/16W; Tolerance: 5%
R1 R13 R290 = RES: Res 200K 1% 1/16W 100PPM 50V 0402; Agile Part Number: RES-00078-01; Barcode: 200041; CIP Link: http://xsjbrdwin1/CIP-E/Component/Index/All?pn=200041; Manufacturer: PANASONIC; Manufacturer PN: ERJ2RKF2003X; Part Type: SMT - 1%; Rated Power: 1/10W; Tolerance: 1%
R14 R18 = RES: Res 68K 1% 1/16W 100PPM 50V 0402; Agile Part Number: RES-00537-01; Barcode: 20000033; CIP Link: http://xsjbrdwin1/CIP-E/Component/Index/All?pn=20000033; Manufacturer: Panasonic Electronic Components; Manufacturer PN: ERJ2RKF6802X; Part Type: RESISTOR; Rated Power: 0.063W, 1/16W; Tolerance: 1%; Datasheet: https://industrial.panasonic.com/cdbs/www-data/pdf/RDA0000/AOA0000C304.pdf
R20 = RES: Res 12K7 1% 1/16W 100PPM 50V 0402; Agile Part Number: RES-00243-01; Barcode: 200261; CIP Link: http://xsjbrdwin1/CIP-E/Component/Index/All?pn=200261; Part Type: SMT - 1%; Rated Power: 1/10W; Tolerance: 1%
R10 R21 R24 R26 = RES: Res 40K2 1% 1/16W 100PPM 50V 0402; ALT_SYMBOLS: RESC100X50X40RND; Agile Part Number: RES-00007-01; Barcode: 200216; CIP Link: http://xsjbrdwin1/CIP-E/Component/Index/All?pn=200216; Manufacturer: PANASONIC; Manufacturer PN: ERJ2RKF4022X; Part Type: SMT - 1%; Rated Power: 1/16W; Tolerance: 1%
R2 R43 = RES: Res 44K2 1% 1/16W 100PPM 50V 0402; ALT_SYMBOLS: 0402; Agile Part Number: RES-00248-01; Barcode: 200266; CIP Link: http://xsjbrdwin1/CIP-E/Component/Index/All?pn=200266; Manufacturer: PANASONIC; Manufacturer PN: ERJ2RKF4422X; Part Type: SMT - 1%; Rated Power: 1/16W; Tolerance: 1%
U1 U2 U72 = MPM3840: DC DC CONVERTER 1.2V; Agile Part Number: ICS-00679-01; Barcode: 50000172; CIP Link: http://xsjbrdwin1/CIP-E/Component/Index/All?pn=50000172; Manufacturer: Monolithic Power Systems Inc.; Part Type: REGULATOR; Datasheet: https://www.monolithicpower.com/pub/media/document/MPM3840_r1.1.pdf
U3-U5 = MPM3810A: IC V. Reg Step-Down DC/DC Synch 6V 1.2A Adj 4.2MHz QFN-12; Agile Part Number: ICS-00678-01; Barcode: 50000173; CIP Link: http://xsjbrdwin1/CIP-E/Component/Index/All?pn=50000173; Manufacturer: Monolithic Power Systems Inc.; Manufacturer PN: MPM3810AGQB-AEC1-Z; Part Type: POWER; Datasheet: https://www.monolithicpower.com/pub/media/document/m/p/mpm3810a-aec1_r1.0.pdf
R16 = RES: Res 34K 1% 1/16W 100PPM 50V 0402; ALT_SYMBOLS: (0402,C402-25,RESC100X50X40L25NRND); Agile Part Number: RES-00307-01; Barcode: 200338; CIP Link: http://xsjbrdwin1/CIP-E/Component/Index/All?pn=200338; Manufacturer: PANASONIC; Manufacturer PN: ERJ2RKF3402X; Part Type: SMT - 1%; Rated Power: 1/16W; Tolerance: 1%

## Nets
5V0_IN: C3.1 C4.1 C6.1 C10.1 C11.1 C20.1 C26.1 C32.1 C33.1 C34.1 C35.1 C39.1 C43.1 C381.1 C382.1 L1.2 R4.1 R12.1 R30.1 R289.1 TP5.1(TP) U1.15(VIN) U2.15(VIN) U3.7(VIN) U4.7(VIN) U5.7(VIN) U7.5(EN) U7.8(IN) U14.1(INP) U14.2(INP) U14.3(INP) U14.12(VBUS) U72.15(VIN) ; also on sheet 12 16 24 25
5V0_IN_EN: R34.2 U6.3(EN)
5V0_IN_FB: R32.1 U6.4(FB)
5V0_IN_SS: C40.1 U6.6(SS)
5V0_IN_SW: C37.2 C319.1 L1.1 U6.16(SW)
5V0_IN_VCC: C38.1 Q21.1(GATE) R265.1 U6.14(VCC)
12V_FAN_GND: C209.1 J13.2(P2) L9.1
12V_FAN_PWR: C210.1 J13.1(P1) L8.1
12V_IN: C30.1 C31.1 C36.1 C203.1 C208.1 D2.1(CATHODE) L8.2 Q5.1(D1) Q5.2(D2) Q5.5(D5) Q5.6(D6) Q5.7(DPAD) R34.1 TP3.1(TP) U6.8(VIN)
12V_IN_JACK: C204.1 C205.1 D1.1(CATHODE) J12.1(CENTER_PWR) R133.1 TP1.1(TP) U41.1-2(VCC)
12V_IN_SOURCE: Q5.4(S4) Q5.8(SPAD) U41.6-7(SOURCE)
AGND1: U6.5(AGND) Z1.2(NET2)
AGND2: U3.11(AGND) Z4.2(NET2)
AGND3: U5.11(AGND) Z5.2(NET2)
AGND4: U4.11(AGND) Z2.2(NET2)
GND: C1.2 C2.2 C3.2 C4.2 C6.2 C7.2 C8.2 C10.2 C11.2 C12.2 C15.2 C16.2 C17.2 C18.2 C19.2 C20.2 C22.2 C23.2 C24.2 C25.2 C26.2 C28.2 C29.2 C30.2 C31.2 C32.2 C33.2 C34.2 C35.2 C36.2 C38.2 C40.2 C42.2 C43.2 C45.2 C48.2 C49.2 C203.2 C204.2 C205.2 C206.2 C207.2 C209.2 C210.2 C234.2 C235.2 C381.2 C382.2 C384.2 C385.2 D1.2(ANODE) J12.2(GND) J15.1(P1) J16.1(P1) J17.1(P1) Q18.2(SOURCE) Q20.2(SOURCE) R2.2 R5.2 R15.2 R16.2 R17.2 R20.2 R23.2 R26.2 R29.2 R31.2 R38.2 R42.2 R43.2 R134.2 R135.2 R223.2 R224.2 R225.2 R261.2 R291.2 R292.2 R293.2 U1.1(GND1) U1.2(GND2) U1.3(GND3) U1.17(GND17) U1.18(GND18) U2.1(GND1) U2.2(GND2) U2.3(GND3) U2.17(GND17) U2.18(GND18) U3.1(PGND1) U3.2(PGND2) U4.1(PGND1) U4.2(PGND2) U5.1(PGND1) U5.2(PGND2) U6.9(PGND) U6.10(PGND) U6.11(PGND) U6.12(PGND) U6.13(PGND) U7.6(GND) U7.9(E_PAD) U8.6(GND) U8.9(E_PAD) U9.6(GND) U9.9(E_PAD) U10.6(GND) U10.9(E_PAD) U12.6(GND) U12.9(E_PAD) U14.4(A1) U14.5(A0) U14.6(GND) U14.11(GND) U41.3(GND) U72.1(GND1) U72.2(GND2) U72.3(GND3) U72.17(GND17) U72.18(GND18) Z1.1(NET1) Z2.1(NET1) Z4.1(NET1) Z5.1(NET1) ; also on sheet 6 7 8 9 10 11 12 13 14 15 16 17 18 19 20 21 22 23 24 25
VCCOEN_PL_M2C: U2.12(EN) U4.9(EN) U72.12(EN) ; also on sheet 6
VCCOEN_PS_M2C: U1.12(EN) U3.9(EN) U5.9(EN) ; also on sheet 6
CC_PL_PGOOD: U2.14(PG) U4.8(PG) U8.3(PG) U9.3(PG) U72.14(PG) ; also on sheet 8 16
CC_PS_PGOOD: U1.14(PG) U3.8(PG) U5.8(PG) U10.3(PG) U12.3(PG) ; also on sheet 8 16
FB_UTIL_3V3: C41.2 R38.1 R39.2 U7.4(FB)
HDA20: Q20.1(GATE) R261.1 ; also on sheet 6
I2C_SCK_LS: U14.9(SCL) ; also on sheet 15 16
I2C_SDA_LS: U14.8(SDA) ; also on sheet 15 16
MP5016_DVDT: C206.1 U41.10(DV/DT)
MP5016_EN: R133.2 U41.9(EN)
MP5016_GATE: C234.1 Q5.3(GATE) U41.8(GATE)
MP5016_ILIMIT: R135.1 U41.4(ILIMIT)
MP5016_MODE: C235.1 R134.1 U41.5(MODE)
PL_1V8: C383.1 C384.1 C385.1 R290.1 TP24.1(TP) U72.7-9(OUT) ; also on sheet 6 7 13 16 20 21
PL_1V8_FB: R290.2 R291.1 U72.10(FB)
PL_1V8_MODE: R289.2 R292.1 U72.13(MODE)
PL_1V8_RAMP: C383.2 U72.11(RAMP)
PL_1V8_SW: C386.1 U72.4-6(SW456)
PL_1V8_SW_NC: U72.16(SW16)
PL_3V3: C9.1 C23.1 C29.1 C45.1 C48.1 R13.1 R471.1 R472.1 TP21.1(TP) U2.7-9(OUT) U8.8(IN) U9.8(IN) ; also on sheet 6 7 10 12 14 15 16 20 21
PL_3V3_FB: R13.2 R43.1 U2.10(FB)
PL_3V3_MODE: R12.2 R42.1 U2.13(MODE)
PL_3V3_RAMP: C9.2 U2.11(RAMP)
PL_3V3_SW: C320.1 U2.4-6(SW456)
PL_3V3_SW_NC: U2.16(SW16)
PL_3V8: C18.1 C19.1 R18.1 TP19.1(TP) U4.5-6(OUT) U4.12(OUT_S) ; also on sheet 13
PL_3V8_FB: R18.2 R20.1 U4.10(FB)
PL_ETH_1V0: C27.1 C28.1 R27.1 TP23.1(TP) U8.1(OUT) ; also on sheet 20 21
PL_ETH_1V0_EN: R471.2 U8.5(EN)
PL_ETH_1V0_FB: C27.2 R27.2 R29.1 U8.4(FB)
PL_ETH_2V5: C21.1 C22.1 R24.1 TP40.1(TP) U9.1(OUT) ; also on sheet 20 21
PL_ETH_2V5_EN: R472.2 U9.5(EN)
PL_ETH_2V5_FB: C21.2 R23.1 R24.2 U9.4(FB)
PS_1V2: C24.1 C25.1 R21.1 TP9.1(TP) U5.5-6(OUT) U5.12(OUT_S) ; also on sheet 24 25
PS_1V2_FB: R21.2 R26.1 U5.10(FB)
PS_1V8: C7.1 C8.1 R14.1 TP15.1(TP) U3.5-6(OUT) U3.12(OUT_S) ; also on sheet 8 9 15 16 17 18 19 24 25
PS_1V8_FB: R14.2 R16.1 U3.10(FB)
PS_3V3: C1.1 C2.1 C5.1 C15.1 C17.1 R1.1 R243.1 R244.1 TP11.1(TP) U1.7-9(OUT) U10.8(IN) U12.8(IN) ; also on sheet 15 16 17 18 19 22 24 25
PS_3V3_FB: R1.2 R2.1 U1.10(FB)
PS_3V3_MODE: R4.2 R5.1 U1.13(MODE)
PS_3V3_RAMP: C5.2 U1.11(RAMP)
PS_3V3_SW: C321.1 U1.4-6(SW456)
PS_3V3_SW_NC: U1.16(SW16)
PS_ETH_1V0: C14.1 C16.1 R6.1 TP17.1(TP) U12.1(OUT) ; also on sheet 18 19
PS_ETH_1V0_EN: R243.2 U12.5(EN)
PS_ETH_1V0_FB: C14.2 R6.2 R17.1 U12.4(FB)
PS_ETH_2V5: C12.1 C13.1 R10.1 TP13.1(TP) U10.1(OUT) ; also on sheet 18 19
PS_ETH_2V5_EN: R244.2 U10.5(EN)
PS_ETH_2V5_FB: C13.2 R10.2 R15.1 U10.4(FB)
PWROFF_C2M_B: C207.1 J12.3(PLUG_DET) Q21.3(DRAIN) U7.3(PG) ; also on sheet 6 8
SOM_5V0: U14.14(INN) U14.15(INN) U14.16(INN) ; also on sheet 6
UTIL_3V3: C41.1 C42.1 C49.1 R39.1 R260.1 TP7.1(TP) U7.1(OUT) U14.10(VS) ; also on sheet 8 14
N1366089: C208.2 D2.2(ANODE) L9.2 Q18.3(DRAIN)
N1766802: R33.1 U6.2(BST)
N1766806: C37.1 R33.2
N1766990: Q21.2(SOURCE) R265.2 U6.7(PG)
N1767106: C39.2 R30.2 R31.1 R32.2
N1767370: C319.2 R223.1
N1784249: C321.2 R225.1
N2390901: Q18.1(GATE) Q20.3(DRAIN) R260.2
N3370406: C320.2 R224.1
N3379104: C386.2 R293.1

Not connected (* = marked no-connect by the designer): U1 19(NC19)* 20(NC20)*; U2 19(NC19)* 20(NC20)*; U3 3-4(NC)*; U4 3-4(NC)*; U5 3-4(NC)*; U6 1(NC)* 15(NC_2)*; U7 2(NC1)* 7(NC2)*; U8 2(NC1)* 7(NC2)*; U9 2(NC1)* 7(NC2)*; U10 2(NC1)* 7(NC2)*; U12 2(NC1)* 7(NC2)*; U14 7(ALERT)* 13(NC)*; U72 19(NC19)* 20(NC20)*

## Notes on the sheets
sheet 1
- SCK-KR-05101
- Robotics Starter Kit Carrier Card
- NOTICE:  These schematics are made available for users who are working with this specific Xilinx board and should
  not be considered an optimal board design reference.  This board was designed for evaluation purposes with
  components that are potentially more complex and costly than would be used in an end customer system.  Users are
  encouraged to leverage the Xilinx design guidelines as the optimal starting point for new board designs.
  © Copyright 2020 Xilinx, Inc. Xilinx, the Xilinx logo, Artix, ISE, Kintex, Spartan, Virtex, Zynq, and other designated
  brands included herein are trademarks of Xilinx in the United States and other countries. [If applicable, insert
  relevant third-party sentence.] All other trademarks are the property of their respective owners.
  DISCLAIMER The information disclosed to you hereunder (the “Materials”) is provided solely for the selection and use
  of Xilinx products. To the maximum extent permitted by applicable law: (1) Materials are made available "AS IS" and with
  all faults, Xilinx hereby DISCLAIMS ALL WARRANTIES AND CONDITIONS, EXPRESS, IMPLIED, OR STATUTORY, INCLUDING BUT NOT LIMITED TO
  WARRANTIES OF MERCHANTABILITY, NON-INFRINGEMENT, OR FITNESS FOR ANY PARTICULAR PURPOSE; and (2) Xilinx shall not be
  liable (whether in contract or tort, including negligence, or under any other theory of liability) for any loss or
  damage of any kind or nature related to, arising under, or in connection with, the Materials (including your use of
  the Materials), including for any direct, indirect, special, incidental, or consequential loss or damage (including loss
  of data, profits, goodwill, or any type of loss or damage suffered as a result of any
  action brought by a third party) even if such damage or loss was reasonably foreseeable or Xilinx had been advised of
  the possibility of the same. Xilinx assumes no obligation to correct any errors contained in the Materials or to notify you
  of updates to the Materials or to product specifications. You may not reproduce, modify, distribute, or publicly display the
  Materials without prior written consent. Certain products are subject to the terms and conditions of Xilinx’s limited
  warranty, please refer to Xilinx’s Terms of Sale which can be viewed at http://www.xilinx.com/legal.htm#tos; IP cores
  may be subject to warranty and support terms contained in a license issued to you by Xilinx. Xilinx products are not designed
  or intended to be fail-safe or for use in any application requiring fail-safe performance; you assume sole risk
  and liability for use of Xilinx products in such critical applications, please refer to Xilinx’s Terms of Sale which can be
  viewed at http://www.xilinx.com/legal.htm#tos.
sheet 2
- POWER BLOCK DIAGRAM
- PERIPHERAL BLOCK DIAGRAM
sheet 3
- 12V FAN HEADER
- 12V DC JACK
- ID: 2.5mm
  OD: 5.5mm
  Depth: 9.0mm
- OVP = 13.2V
  ILIM = 5A
  dV/dt = 1.95V/ms
- 5V0_IN ALWAYS ON REGULATOR
- SOM_5V0 CURRENT MONITOR
- 5V0_IN @5.0V/7A
- SOM_5V0 @5.0V/3A
- INA260 ADDR: 0x40
- POWER TEST POINTS
- UTIL_3V3 ALWAYS ON REGULATOR
- GROUND LOOPS
- UTIL_3V3@3.3V/0.3A
sheet 4
- PS_1V2 @1.2V/1A
- PS_ETH_1V0 @1.0V/0.3A
- PS_ETH_2V5 @2.5V/0.3A
- PS_1V8 @1.8V/0.5A
- POWER TEST POINTS
- PS_3V3 @3.3V/2.5A
sheet 5
- PL_1V8 @1.8V/1.4A
- PL_ETH_1V0 @1.0V/0.3A
- PL_ETH_2V5 @2.5V/0.3A
- PL_3V3 @3.3V/3A
- POWER TEST POINTS
- PL_3V8 @3.8V/1.0A
